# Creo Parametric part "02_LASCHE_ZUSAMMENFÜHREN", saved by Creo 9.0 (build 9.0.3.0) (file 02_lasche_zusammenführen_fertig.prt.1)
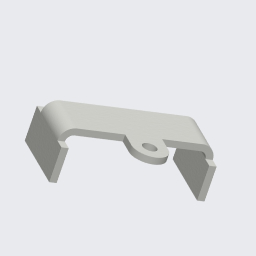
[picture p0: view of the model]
Materials in the file: S235JRG2

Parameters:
  COPY_GEOM_ORIGIN_TYPE = "Part"
  BENENNUNG = "XXX"
  DATUM = "XX.XX.XX"
  ERSTELLER = "ARINDA"
  TEILETYP = "Fertigungsteil"
  SELECT_EN_NAME = "S235JRG2"
  SELECT_DIN_NAME = "RSt37-2"
  SELECT_DIN_NUMBER = "1.0038"
  SELECT_ASTM_NAME = "A 283 M Grade 2"
  MATERIAL_GROUP = "ME_ST_Baustahl"
  STANDARD_EN_DELIVERYSPEC = "DIN EN 10025"
  STANDARD_DIN_DELIVERYSPEC = "DIN 17100"

Other parameters: SMT_PART_BEND_ALLOWANCE_FACTOR, SMT_DFLT_BEND_RADIUS, SMT_DFLT_BEND_ANGLE, SMT_DFLT_CRNR_REL_WIDTH, SMT_DFLT_CRNR_REL_DEPTH, SMT_DFLT_BEND_REL_WIDTH, SMT_DFLT_BEND_REL_DEPTH, SMT_DFLT_BEND_REL_ANGLE, SMT_GAP, SMT_DFLT_EDGE_TREA_WIDTH, SMT_DFLT_MITER_CUT_WIDTH, SMT_DFLT_MITER_CUT_OFFSET, MASSE, SMT_DFLT_BEND_REL_LENGTH, D4, D6

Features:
  1. coordinate system
  2. datum plane "DTM1", "T_RECHTS_Y-Z"
  3. datum plane "DTM2", "T_OBEN_X-Z"
  4. datum plane "DTM3", "T_VORNE_X-Y"
  5. datum axis "A_1"
  6. datum axis "A_2"
  7. datum axis "A_3"
  8. feature "Externe Kopiegeom ID 31"
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
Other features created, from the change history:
  feature "Externe Kopiegeom ID 42"
  feature "Versatz 1(Erste Lasche)"
  feature "Versatz 2"
  feature "Profil 1"
  feature "Laschen Zusammenführen 1" (3 times)
  fill "Planar 1"

Other named items: T_BASIS, A_X-ACHSE, A_Y-ACHSE, A_Z-ACHSE

Layers: 00_STD-ACHSEN, 00_STD-EBENEN, 00_STD-KOORDSYS, 01_ACHSEN, SAMMELFLÄCHEN, VOLUMENGEOMETRIE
